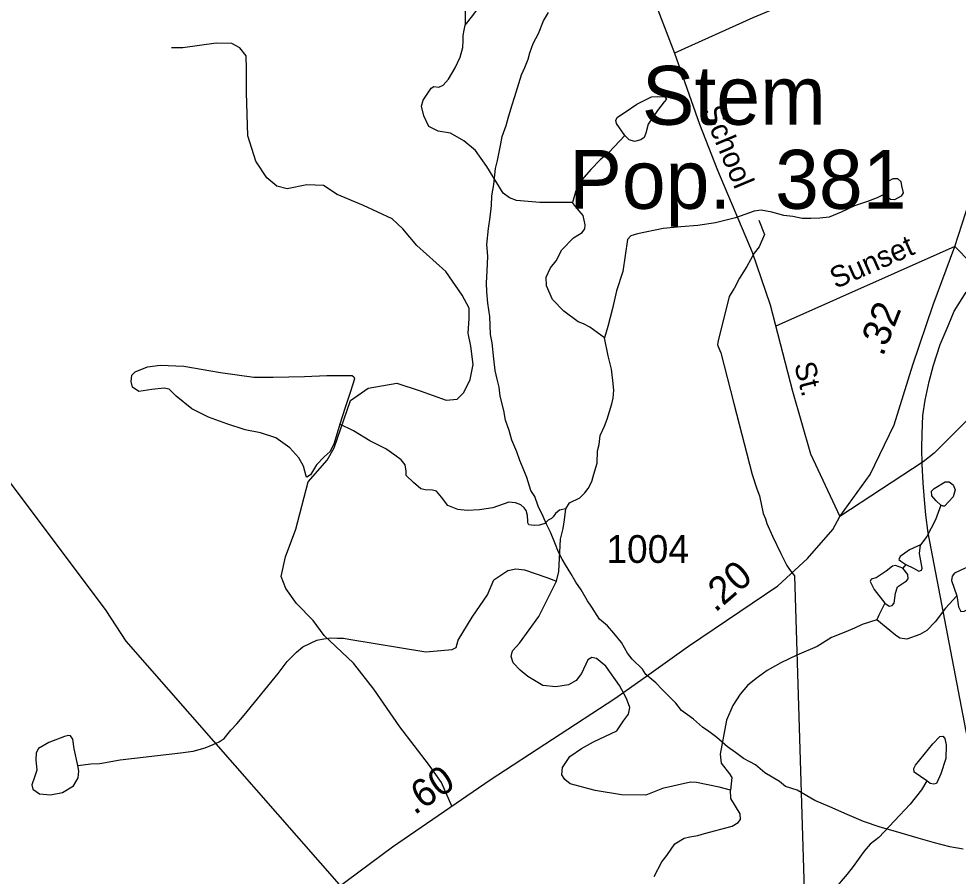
# Model space of a CAD drawing. Extents: x 2056842 to 2160602, y 826753 to 1016856.
# Drawn here: x 2077140 to 2081366, y 889134 to 892991 of the extents above; entities that cross this region are included whole.
import ezdxf

# ---------------------------------------------------------------- set-up
doc = ezdxf.new("R2010")
doc.units = 0
for name, color, linetype in [('Exist Boundary Political City Limit New', 7, 'Continuous'), ('Exist Civil Demographics City Label', 7, 'Continuous'), ('Exist Hydrographic Creek Single Shore', 7, 'Continuous'), ('Exist Hydrographic Misc Water Feature', 7, 'Continuous'), ('Exist Railroad Mainline', 7, 'Continuous'), ('Exist Road Non-System Type 51', 7, 'Continuous'), ('Exist Road Non-System Type 51 Label', 7, 'Continuous'), ('Exist Road Secondary Mileage Hundredths English Label', 7, 'Continuous'), ('Exist Road Secondary Type 51 Attributed', 7, 'Continuous'), ('Exist Road Secondary Type 51 Number Label', 7, 'Continuous'), ('Exist Utilities Electrical Transmission Line', 7, 'Continuous'), ('Map Preparation Boundary City Limit Buffer Line', 7, 'Continuous')]:
    doc.layers.add(name, color=color, linetype=linetype)

msp = doc.modelspace()

# ---------------------------------------------------------------- linework, layer by layer
at = {"layer": 'Exist Boundary Political City Limit New'}
for points in [[(2079878.6, 890136.9), (2079850.6, 890184.8), (2079816.5, 890226.8), (2079788.5, 890260.5), (2079752.2, 890290.5), (2079718.1, 890344.4), (2079698, 890372.2), (2079670, 890422.2), (2079645.9, 890456.1), (2079623.6, 890496), (2079599.5, 890533.9), (2079583.5, 890559.8), (2079567.2, 890591.9), (2079551.1, 890633.9), (2079531.1, 890681.8), (2079513, 890717.8), (2079499, 890751.6), (2079476.8, 890797.6), (2079460.6, 890841.6), (2079442.5, 890869.4), (2079424.4, 890927.3), (2079408.2, 890967.3), (2079394.1, 891003.2), (2079380, 891043.3), (2079357.9, 891095.1), (2079345.8, 891139.2), (2079329.5, 891185.1), (2079321.5, 891229.1), (2079305.1, 891293), (2079301.1, 891332.9), (2079291, 891368.9), (2079283, 891408.9), (2079276.6, 891460.8), (2079268.5, 891532.8), (2079262.2, 891570.8), (2079258.1, 891650.8), (2079250, 891710.8), (2079245.6, 891762.7), (2079243.6, 891802.8), (2079247.4, 891854.7), (2079249.1, 891922.7), (2079245, 891974.8), (2079253, 892046.8), (2079260.6, 892098.6), (2079266.5, 892150.7), (2079268.4, 892194.7), (2079276.2, 892244.7), (2079284, 892316.8), (2079293.9, 892352.8), (2079307.6, 892428.9), (2079313.5, 892460.8), (2079331.4, 892510.8), (2079341.1, 892543), (2079357.1, 892598.9), (2079371, 892641), (2079388.9, 892699.1), (2079400.6, 892739), (2079416.5, 892771.1), (2079430.5, 892809.2), (2079438.2, 892837.3), (2079454.1, 892879.3), (2079478.1, 892925.2), (2079499.9, 892981.4), (2079521.9, 893019.5)], [(2081387.4, 889255.8), (2081327.4, 889265.4), (2081259.1, 889283.2), (2081185.1, 889305), (2081083.1, 889334.8), (2081015, 889354.5), (2080939, 889380.3), (2080866.9, 889412), (2080788.9, 889445.8), (2080720.6, 889473.6), (2080640.6, 889520.4), (2080588.5, 889537.1), (2080562.4, 889559.1), (2080528.4, 889579), (2080495.4, 889598.9), (2080454.1, 889634.8), (2080428.2, 889648.8), (2080400.1, 889662.6), (2080364, 889690.4), (2080328, 889716.3), (2080279.9, 889758.1), (2080243.9, 889784.1), (2080215.9, 889804.1), (2080175.5, 889839.9), (2080121.5, 889879.6), (2080095.5, 889911.6), (2080065.2, 889941.4), (2080033.4, 889973.5), (2080005.1, 890003.2), (2079961.1, 890041.2), (2079945, 890065.1), (2079898.8, 890110.8), (2079878.6, 890136.9)]]:
    msp.add_lwpolyline(points, dxfattribs=at)
at = {"layer": 'Exist Hydrographic Creek Single Shore'}
for points in [[(2079148.3, 892962.7), (2079182.5, 893005.2), (2079234.8, 893077.6), (2079342.1, 893161.2), (2079395.8, 893189.9), (2079409.5, 893223.6), (2079410.7, 893238.6), (2079392, 893294.7), (2079343.4, 893385.9), (2079309.2, 893464.5)], [(2078639.3, 893378.6), (2078712.9, 893421.1), (2078746.6, 893439.8), (2078767.8, 893446), (2078792.8, 893443.5), (2078815.2, 893433.5), (2078848.9, 893392.3), (2078885.9, 893306.9), (2078899.8, 893282.8), (2078920.3, 893265.2), (2078954.2, 893259.3), (2079030, 893253.4), (2079062.4, 893243.7), (2079098.3, 893213.8), (2079132.1, 893151.2), (2079140.8, 893115), (2079147, 893070.1), (2079148.3, 892962.7)], [(2079630, 892164.7), (2079483.3, 892164.7), (2079378.6, 892173.4), (2079347.4, 892184.7), (2079318.7, 892205.9), (2079245.1, 892326.9), (2079193.9, 892398.6), (2079141.5, 892441), (2079081.7, 892476), (2079025.5, 892484.7), (2078984.4, 892506.4), (2078961.9, 892553.9), (2078950.7, 892597.5), (2078959.4, 892625), (2078994.3, 892678.7), (2079006.8, 892686.2), (2079029.3, 892682.4), (2079049.2, 892692.4), (2079072.9, 892718.6), (2079102.9, 892769.8), (2079125.3, 892818.5), (2079136.6, 892862.1), (2079139.2, 892891.5), (2079139, 892915.8), (2079143.3, 892939), (2079148.3, 892962.7)], [(2079866.3, 892465.5), (2079794.7, 892389.9), (2079755.1, 892355.8), (2079713.3, 892313.5), (2079672.4, 892265.8), (2079646.3, 892217.1), (2079630, 892164.7)], [(2081037.6, 892203.4), (2081001.5, 892185.9), (2080957.1, 892169.5), (2080899.5, 892149.4), (2080839.4, 892121.2), (2080785.7, 892098.9), (2080743.5, 892093.1), (2080703.5, 892092.7), (2080663.5, 892092.7), (2080621.5, 892100.6), (2080581.7, 892106.3), (2080527.5, 892120.2), (2080479.4, 892130.4), (2080447.6, 892125.8), (2080363.5, 892095.6), (2080273.7, 892073.4), (2080193.9, 892061.2), (2080118.1, 892054.9), (2080038.1, 892046.7), (2079923.2, 892023.6), (2079893.7, 892014.7), (2079877.5, 891997.2), (2079856.3, 891853.6), (2079828.9, 891767.5), (2079810.9, 891688), (2079789.1, 891606), (2079775.2, 891555.3)], [(2079775.2, 891555.3), (2079709.1, 891604), (2079680.4, 891619), (2079655.5, 891627.2), (2079591.9, 891675.9), (2079540.7, 891728.3), (2079513.3, 891789.5), (2079512, 891828.2), (2079532, 891870.6), (2079556.9, 891901.8), (2079583.1, 891951.7), (2079635.5, 892005.4), (2079674.2, 892029.1), (2079685.4, 892045.4), (2079687.9, 892064.1), (2079677.9, 892106.5), (2079643.8, 892146), (2079630, 892164.7)], [(2079600.3, 890785.7), (2079617.6, 890813.5), (2079663.6, 890835.5), (2079685.4, 890857.7), (2079701.2, 890877.7), (2079717.3, 890909.5), (2079727.2, 890941.8), (2079741, 890991.7), (2079742.8, 891047.8), (2079750.6, 891075.8), (2079754.7, 891115.8), (2079774.6, 891157.7), (2079786.4, 891189.9), (2079808.2, 891258.1), (2079814, 891283.9), (2079816, 891319.9), (2079811.7, 891364), (2079805.8, 891414), (2079791.7, 891474), (2079775.2, 891555.3)], [(2079600.3, 890785.7), (2079571.7, 890780.7), (2079554.2, 890765.8), (2079543.7, 890751), (2079535.7, 890743), (2079521.8, 890735), (2079506, 890720.9), (2079481.9, 890712.9), (2079457.9, 890710.8), (2079434.1, 890714.9), (2079430, 890722.8), (2079429.8, 890730.7), (2079427.7, 890756.7), (2079421.6, 890778.8), (2079413.6, 890790.8), (2079397.5, 890804.6), (2079373.8, 890813.2), (2079343.9, 890815.7), (2079271.5, 890790.7), (2079211.6, 890782), (2079156.8, 890778.2), (2079114.3, 890783.2), (2079069.4, 890802), (2079040.7, 890838.1), (2079018.3, 890865.6), (2079000.8, 890870.6), (2078967.1, 890871.8), (2078948.4, 890876.8), (2078916, 890904.3), (2078882.3, 890936.8), (2078882.3, 890955.5), (2078877.3, 890984.2), (2078859.9, 891006.6), (2078831.2, 891027.9), (2078790.3, 891056.8), (2078719.2, 891091.8), (2078645.6, 891136.7), (2078583.2, 891166.7)], [(2077405.4, 889631.9), (2077463.4, 889638.8), (2077503.6, 889640.8), (2077595.7, 889657.2), (2077867.4, 889688.3), (2077923.6, 889696.4), (2077951.5, 889704.3), (2077977.3, 889710.5), (2078013.4, 889726.6), (2078041.5, 889738.6), (2078063.2, 889752.7), (2078093, 889790.8), (2078121, 889819), (2078152.8, 889858.9), (2078306.2, 890045.4), (2078346.2, 890099.4), (2078388.2, 890141.8), (2078418, 890165.5), (2078451.8, 890181.9), (2078479.7, 890196), (2078511.7, 890202.1), (2078543.9, 890206.1), (2078572, 890204.3), (2078600.1, 890204.5), (2078624, 890200.5), (2078970.9, 890143.7), (2079089.4, 890153.7), (2079106.9, 890162.4), (2079116.8, 890194.9), (2079179.2, 890299.7), (2079247.8, 890399.8), (2079276.5, 890467.2), (2079340.1, 890509.6), (2079375.1, 890515.9), (2079415, 890512.1), (2079514.8, 890477.2), (2079558.4, 890461)], [(2080341.1, 889521.4), (2080289.9, 889533.8), (2080188.9, 889555.1), (2080161.4, 889556.3), (2080035.4, 889528.8), (2079960.6, 889497.6), (2079851.6, 889499.6), (2079733.1, 889519.6), (2079619.6, 889549.6), (2079595.9, 889568.3), (2079582.1, 889589.5), (2079585.9, 889623.2), (2079618.3, 889671.9), (2079670.7, 889708.1), (2079724.9, 889737.6), (2079830.6, 889788.3), (2079860.7, 889832.3), (2079882.8, 889862.1), (2079887.8, 889893.3), (2079872.8, 889933.2), (2079842.3, 889991.4), (2079780, 890078.8), (2079738.8, 890113.7), (2079717.6, 890117.5), (2079698.9, 890107.5), (2079671.4, 890045.1), (2079647.7, 890013.9), (2079612.8, 889993.9), (2079555.4, 889985.2), (2079496.8, 889991.4), (2079429.4, 890032.6), (2079394.5, 890060.1), (2079363.3, 890093.8), (2079354.6, 890122.5), (2079360.8, 890147.4), (2079392, 890182.4), (2079479.3, 890302.2), (2079558.4, 890461)], [(2081225.3, 889562.5), (2081201.3, 889522.8), (2081149.9, 889458.3), (2081008.4, 889308.1), (2080970.2, 889277.9), (2080942.4, 889246), (2080922.7, 889219.7), (2080892.7, 889177.6), (2080866.7, 889143.4), (2080839.3, 889111.5), (2080816.8, 889084), (2080787.1, 889059.3), (2080765, 889043.2), (2080729.5, 889029.1), (2080700.8, 889025.3), (2080667.2, 889027.8), (2080623.5, 889016.6), (2080577.3, 888985.4), (2080561.1, 888936.7), (2080552.4, 888878.1), (2080547.4, 888836.9)], [(2079998.3, 889132.4), (2080032.5, 889199.1), (2080054.9, 889226.5), (2080091.1, 889279), (2080132.3, 889304.9), (2080158.1, 889311.3), (2080194.3, 889317.4), (2080224.3, 889325.3), (2080349.3, 889358.6), (2080375.5, 889374.8), (2080386.7, 889388.6), (2080384.2, 889414.8), (2080342.3, 889483.9), (2080341.1, 889521.4)]]:
    msp.add_lwpolyline(points, dxfattribs=at)
at = {"layer": 'Exist Hydrographic Misc Water Feature'}
for points in [[(2079866.3, 892465.5), (2079828.9, 892519.2), (2079825.1, 892535.4), (2079832.6, 892547.9), (2079867.5, 892570.3), (2079919.9, 892606.5), (2079986.1, 892639), (2080013.5, 892641.5), (2080045.9, 892639), (2080053.4, 892629), (2080043.4, 892617.8), (2080012.2, 892577.8), (2079971.1, 892516.7), (2079959.9, 892475.5), (2079953.6, 892456.7), (2079938.6, 892446.8), (2079910, 892439.3), (2079885, 892446.8), (2079866.3, 892465.5)], [(2081037.6, 892203.4), (2081032.6, 892237.1), (2081040.1, 892254.5), (2081072.6, 892272), (2081092.5, 892272), (2081107.5, 892258.3), (2081111.2, 892239.6), (2081117.5, 892207.1), (2081108.7, 892192.1), (2081078.8, 892175.9), (2081061.3, 892177.2), (2081050.1, 892185.9), (2081037.6, 892203.4)], [(2078583.2, 891166.7), (2078558.2, 891082.3), (2078540.8, 891044.8), (2078513.3, 891019.9), (2078478.4, 890983.7), (2078452.2, 890939), (2078436, 890929), (2078432.3, 890932.8), (2078419.8, 890977.7), (2078399.8, 891016.4), (2078358.7, 891061.3), (2078296.3, 891105), (2078226.4, 891128.7), (2078157.8, 891141.2), (2078075.5, 891168.7), (2077993.2, 891198.6), (2077918.3, 891236.1), (2077847.2, 891293.5), (2077816, 891324.7), (2077793.6, 891329.7), (2077737.4, 891323.4), (2077679.8, 891313.4), (2077651.1, 891333.4), (2077644.9, 891358.4), (2077648.6, 891387.1), (2077663.6, 891402.1), (2077718.5, 891425.8), (2077775.9, 891432), (2077881.9, 891428.3), (2078046.5, 891399.6), (2078197.5, 891378.3), (2078283.6, 891378.3), (2078424.5, 891382.1), (2078525.1, 891385.8), (2078639.8, 891385.8), (2078647.3, 891380.8), (2078649.8, 891370.9), (2078631.1, 891313.4), (2078607.4, 891242.3), (2078583.2, 891166.7)], [(2081287.9, 890803.5), (2081266.7, 890822.2), (2081246.7, 890844.6), (2081245.5, 890865.9), (2081257.9, 890878.3), (2081306.6, 890908.3), (2081325.3, 890908.3), (2081342.8, 890894.6), (2081352.7, 890872.1), (2081342.8, 890839.6), (2081304.1, 890798.5), (2081297.8, 890798.5), (2081287.9, 890803.5)], [(2081287.9, 890803.5), (2081262.9, 890737.3), (2081224.3, 890662.4), (2081195.6, 890625)], [(2079558.4, 890461), (2079569.7, 890504.6), (2079576.1, 890649.3), (2079582.9, 890674.6), (2079589.1, 890698.4), (2079594.1, 890737), (2079600.3, 890785.7)], [(2081195.6, 890625), (2081146.9, 890601.3), (2081104.5, 890572.5), (2081098.3, 890558.8), (2081107, 890551.3), (2081129.4, 890536.3)], [(2081129.4, 890536.3), (2081164.4, 890518.9), (2081189.3, 890506.4), (2081200.5, 890510.1), (2081203, 890520.1), (2081191.8, 890585), (2081195.6, 890625)], [(2081117, 890518.9), (2081083.3, 890531.4), (2081070.8, 890528.9), (2081042.1, 890506.4), (2080997.2, 890476.4), (2080974.8, 890470.2), (2080969.8, 890459), (2080987.2, 890422.8), (2081035.9, 890361.6), (2081055.8, 890349.1), (2081068.3, 890351.6), (2081077.1, 890361.6), (2081083.3, 890406.5), (2081093.3, 890435.2), (2081133.2, 890462.7), (2081140.7, 890471.4), (2081139.4, 890491.4), (2081117, 890518.9)], [(2081129.4, 890536.3), (2081117, 890518.9)], [(2081359, 890395.1), (2081367.7, 890345.1), (2081377.7, 890325.2), (2081392.7, 890326.4), (2081408.9, 890335.1), (2081435.1, 890376.3), (2081463.8, 890453.7), (2081486.2, 890489.9), (2081492.4, 890514.9), (2081483.7, 890527.4), (2081463.8, 890533.6), (2081397.6, 890519.9), (2081349, 890497.4), (2081339, 890483.7), (2081335.3, 890463.7), (2081359, 890395.1)], [(2081359, 890395.1), (2081309.1, 890340.1), (2081261.7, 890277.7), (2081224.3, 890239), (2081193.1, 890220.3), (2081135.3, 890200.3), (2081103.7, 890204.3), (2081083.4, 890217.9), (2080999.7, 890287.7)], [(2081035.9, 890361.6), (2081008.4, 890307.7), (2080999.7, 890287.7)], [(2080999.7, 890287.7), (2080933.3, 890265.5), (2080899.3, 890249.5), (2080853.4, 890229.3), (2080795.7, 890207.2), (2080731.6, 890167), (2080640, 890128), (2080567.6, 890093), (2080506.5, 890059.3), (2080456.6, 890023.1), (2080418.4, 889991.9), (2080384.7, 889952), (2080352.3, 889902), (2080323.6, 889835.9), (2080294.9, 889683.4), (2080298.7, 889642.2), (2080337.3, 889594.7), (2080347.3, 889577.3), (2080341.1, 889521.4)], [(2077405.4, 889631.9), (2077389.2, 889706.8), (2077382.9, 889750.5), (2077372.9, 889765.5), (2077363, 889766.7), (2077345.5, 889761.7), (2077274.4, 889735.5), (2077228.2, 889708.1), (2077217, 889688.1), (2077215.8, 889656.9), (2077220.7, 889610.7), (2077209.5, 889579.5), (2077198.3, 889544.6), (2077202, 889524.6), (2077233.2, 889504.6), (2077281.9, 889499.6), (2077335.5, 889509.6), (2077385.4, 889540.8), (2077406.6, 889577), (2077409.1, 889605.7), (2077405.4, 889631.9)], [(2081225.3, 889562.5), (2081167.9, 889602.5), (2081165.4, 889618.7), (2081172.9, 889633.7), (2081251.4, 889729.8), (2081282.6, 889762.2), (2081296.4, 889763.5), (2081306.3, 889753.5), (2081311.3, 889724.8), (2081310.1, 889663.6), (2081287.6, 889593.7), (2081267.7, 889551.3), (2081256.4, 889547.6), (2081239, 889551.3), (2081225.3, 889562.5)]]:
    msp.add_lwpolyline(points, dxfattribs=at)
at = {"layer": 'Exist Railroad Mainline'}
msp.add_lwpolyline([(2081543.9, 889042.2), (2081230.8, 890679), (2081220.6, 890759), (2081214.4, 890827), (2081208.2, 890902.9), (2081203.9, 890987), (2081201.6, 891059), (2081203.6, 891123), (2081207.3, 891206.9), (2081216.9, 891274.9), (2081234.6, 891359), (2081254.6, 891433), (2081284.3, 891525.2), (2081320, 891609.3), (2081347.8, 891675.3), (2081401.4, 891761.6)], dxfattribs=at)
at = {"layer": 'Exist Road Non-System Type 51'}
for points in [[(2079032.7, 893548.8), (2079214, 893455), (2079332.7, 893436.2), (2079507.7, 893442.5), (2079657.7, 893423.7), (2079789, 893367.4), (2079907.7, 893267.3), (2079976.5, 893129.7), (2080089, 892835.8), (2080201.5, 892516.8), (2080282.7, 892310.4), (2080439, 891941.4), (2080520.2, 891703.7), (2080620.2, 891316), (2080701.5, 891033.3), (2080833.5, 890752.3)], [(2081422.7, 893306.8), (2080973.7, 893188.8), (2080701.4, 893104), (2080441.1, 892995), (2080089, 892835.8)], [(2079087.7, 889448.1), (2079041.6, 889554.6), (2078982.1, 889638.1), (2078854, 889805.1), (2078737, 889975.7), (2078644.7, 890092), (2078513.6, 890217.2), (2078463.7, 890283.5), (2078389.2, 890361), (2078341.5, 890428.1), (2078319.2, 890481.8), (2078340.1, 890569.7), (2078386.2, 890694.9), (2078442.1, 890907.3), (2078527, 891005.7), (2078558.3, 891060.9), (2078631.3, 891274), (2078711, 891328.4), (2078840.5, 891352.3), (2078944.8, 891316.5), (2079062.5, 891274.8), (2079111.6, 891279.2), (2079141.4, 891309), (2079169.7, 891368.7), (2079183.1, 891435.7), (2079172.7, 891517.7), (2079160.8, 891575.9), (2079166, 891642.2), (2079166, 891688.4), (2079134.7, 891748), (2079060.3, 891853.9), (2078930.7, 891971.6), (2078866.6, 892046.1), (2078818.9, 892090.9), (2078690.1, 892151.2), (2078572.4, 892200.4), (2078509.9, 892240.7), (2078435.4, 892243.6), (2078347.5, 892225.8), (2078299.8, 892237.7), (2078255.1, 892274.9), (2078206, 892349.5), (2078170.2, 892464.2), (2078163.5, 892658.8), (2078163.5, 892766.1), (2078162, 892824.2), (2078133.7, 892860), (2078098, 892879.4), (2078028, 892880.9), (2077877.5, 892860), (2077826.9, 892860)], [(2081349.9, 891966.6), (2080545, 891607.8)], [(2081349.9, 891966.6), (2081711.5, 891598.2)]]:
    msp.add_lwpolyline(points, dxfattribs=at)
at = {"layer": 'Exist Road Secondary Type 51 Attributed'}
for points in [[(2080833.5, 890752.3), (2080970, 890941), (2081077.8, 891164), (2081161.3, 891434.5), (2081252.9, 891704.2), (2081349.9, 891966.6), (2081433.5, 892221)], [(2081882.6, 891838), (2081755, 891663.7), (2081613.1, 891449.8), (2081403.8, 891182.8), (2081258.3, 891037.2), (2081207.9, 890997.5), (2080833.5, 890752.3)], [(2077276.6, 887836.5), (2077382.6, 888021.6), (2077486.8, 888165.4), (2077603.5, 888275.1), (2077866.7, 888547.4), (2078094.9, 888725.4), (2078301.4, 888880), (2078821.5, 889265.6), (2079260.7, 889566.7), (2079820.3, 889932.5), (2079963.9, 890034.3), (2080152.6, 890168), (2080554.1, 890440.4), (2080687.1, 890562.6), (2080802, 890693.9), (2080833.5, 890752.3)]]:
    msp.add_lwpolyline(points, dxfattribs=at)
at = {"layer": 'Exist Utilities Electrical Transmission Line'}
for points in [[(2070228.8, 900032.1), (2072358.2, 897262.8), (2073244.3, 896042.6), (2073834.2, 895260.3), (2077530.5, 890329.4), (2077620.9, 890191.7), (2078985.5, 888634.2), (2079057.9, 888552.5), (2080356.6, 887331.2), (2080736.5, 886973.8)], [(2080468.6, 892084.5), (2080494.7, 892020.6), (2080470.9, 891964.6), (2080447.1, 891936.5), (2080415.3, 891876.4), (2080381.4, 891824.3), (2080357.4, 891778.2), (2080356.6, 891776.7), (2080335.7, 891742.2), (2080329.8, 891716.1), (2080286.2, 891544), (2080282.4, 891524.1), (2080286.4, 891516), (2080298.4, 891488.2), (2080356.6, 891260.4), (2080438.1, 890940.6), (2080460.4, 890876.7), (2080472.3, 890844.7), (2080488.7, 890764.7), (2080498.8, 890740.7), (2080504.8, 890720.8), (2080531, 890662.9), (2080567.2, 890585.1), (2080595.5, 890531.1), (2080607.5, 890513.1), (2080629.5, 890485.2), (2080736.5, 886973.8)]]:
    msp.add_lwpolyline(points, dxfattribs=at)
at = {"layer": 'Map Preparation Boundary City Limit Buffer Line'}
for points in [[(2079878.6, 890136.9), (2079850.6, 890184.8), (2079816.5, 890226.8), (2079788.5, 890260.5), (2079752.2, 890290.5), (2079718.1, 890344.4), (2079698, 890372.2), (2079670, 890422.2), (2079645.9, 890456.1), (2079623.6, 890496), (2079599.5, 890533.9), (2079583.5, 890559.8), (2079567.2, 890591.9), (2079551.1, 890633.9), (2079531.1, 890681.8), (2079513, 890717.8), (2079499, 890751.6), (2079476.8, 890797.6), (2079460.6, 890841.6), (2079442.5, 890869.4), (2079424.4, 890927.3), (2079408.2, 890967.3), (2079394.1, 891003.2), (2079380, 891043.3), (2079357.9, 891095.1), (2079345.8, 891139.2), (2079329.5, 891185.1), (2079321.5, 891229.1), (2079305.1, 891293), (2079301.1, 891332.9), (2079291, 891368.9), (2079283, 891408.9), (2079276.6, 891460.8), (2079268.5, 891532.8), (2079262.2, 891570.8), (2079258.1, 891650.8), (2079250, 891710.8), (2079245.6, 891762.7), (2079243.6, 891802.8), (2079247.4, 891854.7), (2079249.1, 891922.7), (2079245, 891974.8), (2079253, 892046.8), (2079260.6, 892098.6), (2079266.5, 892150.7), (2079268.4, 892194.7), (2079276.2, 892244.7), (2079284, 892316.8), (2079293.9, 892352.8), (2079307.6, 892428.9), (2079313.5, 892460.8), (2079331.4, 892510.8), (2079341.1, 892543), (2079357.1, 892598.9), (2079371, 892641), (2079388.9, 892699.1), (2079400.6, 892739), (2079416.5, 892771.1), (2079430.5, 892809.2), (2079438.2, 892837.3), (2079454.1, 892879.3), (2079478.1, 892925.2), (2079499.9, 892981.4), (2079521.9, 893019.5)], [(2081387.4, 889255.8), (2081327.4, 889265.4), (2081259.1, 889283.2), (2081185.1, 889305), (2081083.1, 889334.8), (2081015, 889354.5), (2080939, 889380.3), (2080866.9, 889412), (2080788.9, 889445.8), (2080720.6, 889473.6), (2080640.6, 889520.4), (2080588.5, 889537.1), (2080562.4, 889559.1), (2080528.4, 889579), (2080495.4, 889598.9), (2080454.1, 889634.8), (2080428.2, 889648.8), (2080400.1, 889662.6), (2080364, 889690.4), (2080328, 889716.3), (2080279.9, 889758.1), (2080243.9, 889784.1), (2080215.9, 889804.1), (2080175.5, 889839.9), (2080121.5, 889879.6), (2080095.5, 889911.6), (2080065.2, 889941.4), (2080033.4, 889973.5), (2080005.1, 890003.2), (2079961.1, 890041.2), (2079945, 890065.1), (2079898.8, 890110.8), (2079878.6, 890136.9)]]:
    msp.add_lwpolyline(points, dxfattribs=at)

# ---------------------------------------------------------------- texts
at = {"layer": 'Exist Civil Demographics City Label'}
for s, p in [('Stem', (2079942.6, 892513.9)), ('Pop.  381', (2079616.1, 892136))]:
    msp.add_text(s, height=265, dxfattribs=at).set_placement(p)
at = {"layer": 'Exist Road Non-System Type 51 Label'}
for s, rotation, p in [('School', 292.7396, (2080212.5, 892577.1)), ('Sunset', 23.7823, (2080814.4, 891775)), ('St.', 284.2632, (2080627, 891435.2))]:
    msp.add_text(s, height=95, rotation=rotation, dxfattribs=at).set_placement(p)
at = {"layer": 'Exist Road Secondary Mileage Hundredths English Label'}
for s, rotation, p in [('.32', 68.6227, (2081026.9, 891468.3)), ('.20', 40.8376, (2080272.6, 890317.1)), ('.60', 34.2225, (2078919.3, 889406.6))]:
    msp.add_text(s, height=125, rotation=rotation, dxfattribs=at).set_placement(p)
at = {"layer": 'Exist Road Secondary Type 51 Number Label'}
msp.add_text('1004', height=125, dxfattribs=at).set_placement((2079782.8, 890543))

doc.saveas('drawing.dxf')
